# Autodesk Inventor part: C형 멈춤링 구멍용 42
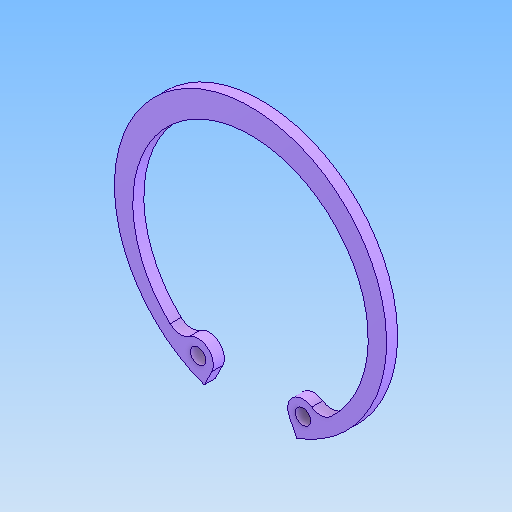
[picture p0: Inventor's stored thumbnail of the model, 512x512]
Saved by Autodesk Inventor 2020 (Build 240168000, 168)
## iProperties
Created: 2025-11
Part Number: C형 멈춤링 구멍용 42
Material: 강철, 연강
Description: 리테이닝 링(C형)
Document SubType Name: Modeling
Designer: PC2-06
Density: 7.85 g/cm^3
Appearance: 기본값
Author: jhkim
Sending System: Autodesk Inventor 2026
Preprocessor: ST-DEVELOPER v20.1
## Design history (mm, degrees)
feature "Solid1"
node "솔리드1"
